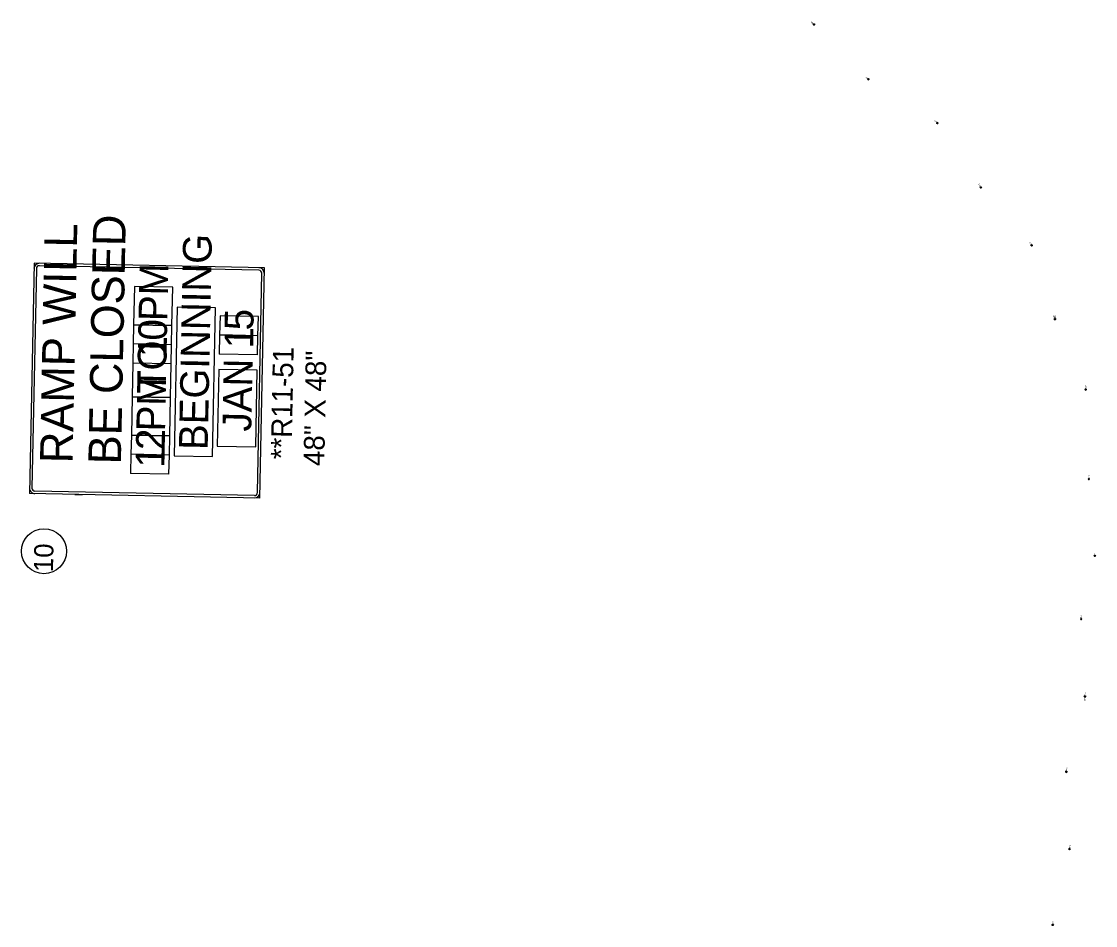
# Model space of a CAD drawing. Extents: x 335726 to 369746, y 119154 to 200788.
# Drawn here: x 351741 to 360135, y 171246 to 178312 of the extents above; entities that cross this region are included whole.
import ezdxf

# ---------------------------------------------------------------- set-up
doc = ezdxf.new("R2010")
doc.units = 0
for name, color, linetype in [('CA-TEXT', 7, 'Continuous'), ('E_SOIL_BORE1 [KAPUR_CADDS_LEVELS]', 7, 'Continuous'), ('E_SOIL_BORE2 [KAPUR_CADDS_LEVELS]', 7, 'Continuous'), ('P_MARK', 7, 'Continuous'), ('P_SGN_Cell', 7, 'Continuous')]:
    doc.layers.add(name, color=color, linetype=linetype)

msp = doc.modelspace()

# ---------------------------------------------------------------- linework, layer by layer
at = {"layer": 'CA-TEXT'}
msp.add_circle((351916.8, 174171.5), 175.9, dxfattribs=at)
at = {"layer": 'P_MARK'}
for p, q in [((357929.4, 178289.2), (357939.4, 178289.2)), ((357934.4, 178294.2), (357934.4, 178284.2)), ((358358.8, 177866.6), (358358.8, 177856.6)), ((358353.8, 177861.6), (358363.8, 177861.6)), ((358893.7, 177517.5), (358903.7, 177517.5)), ((358898.7, 177522.5), (358898.7, 177512.5)), ((359233.3, 177015.2), (359243.3, 177015.2)), ((359238.3, 177020.2), (359238.3, 177010.2)), ((359630.4, 176562.4), (359640.4, 176562.4)), ((359635.4, 176567.4), (359635.4, 176557.4)), ((359812.5, 175985.9), (359822.5, 175985.9)), ((359817.5, 175990.9), (359817.5, 175980.9)), ((360052.2, 175435.6), (360062.2, 175435.6)), ((360057.2, 175440.6), (360057.2, 175430.6)), ((360077.6, 174734.7), (360087.6, 174734.7)), ((360082.6, 174739.7), (360082.6, 174729.7)), ((360124, 174136), (360134, 174136)), ((360129, 174141), (360129, 174131)), ((360017.5, 173640.8), (360027.5, 173640.8)), ((360022.5, 173645.8), (360022.5, 173635.8)), ((360047.1, 173036.8), (360057.1, 173036.8)), ((360052.1, 173041.8), (360052.1, 173031.8)), ((359901.4, 172447.6), (359911.4, 172447.6)), ((359906.4, 172452.6), (359906.4, 172442.6)), ((359926.5, 171844), (359936.5, 171844)), ((359931.5, 171849), (359931.5, 171839)), ((359795.3, 171250.9), (359805.3, 171250.9)), ((359800.3, 171255.9), (359800.3, 171245.9))]:
    msp.add_line(p, q, dxfattribs=at)
for centre in [(357934.4, 178289.2), (358358.8, 177861.6), (358898.7, 177517.5), (359238.3, 177015.2), (359635.4, 176562.4), (359817.5, 175985.9), (360057.2, 175435.6), (360082.6, 174734.7), (360129, 174136), (360022.5, 173640.8), (360052.1, 173036.8), (359906.4, 172447.6), (359931.5, 171844), (359800.3, 171250.9)]:
    msp.add_circle(centre, 5, dxfattribs=at)
for centre, radius, start, end in [((357934.4, 178289.2), 4.5, 89.98693, 179.98693), ((357934.4, 178289.2), 4, 89.98693, 179.98693), ((357934.4, 178289.2), 3.5, 89.98693, 179.98693), ((357934.4, 178289.2), 3, 89.98693, 179.98693), ((357934.4, 178289.2), 2.5, 89.98693, 179.98693), ((357934.4, 178289.2), 2, 89.98693, 179.98693), ((357934.4, 178289.2), 1.5, 89.98693, 179.98693), ((357934.4, 178289.2), 1, 89.98693, 179.98693), ((357934.4, 178289.2), 0.5, 89.98693, 179.98693), ((357934.4, 178289.2), 4.5, 269.98693, 359.98693), ((357934.4, 178289.2), 4, 269.98693, 359.98693), ((357934.4, 178289.2), 3.5, 269.98693, 359.98693), ((357934.4, 178289.2), 3, 269.98693, 359.98693), ((357934.4, 178289.2), 2.5, 269.98693, 359.98693), ((357934.4, 178289.2), 2, 269.98693, 359.98693), ((357934.4, 178289.2), 1.5, 269.98693, 359.98693), ((357934.4, 178289.2), 1, 269.98693, 359.98693), ((357934.4, 178289.2), 0.5, 269.98693, 359.98693), ((358358.8, 177861.6), 4.5, 89.98693, 179.98693), ((358358.8, 177861.6), 4, 89.98693, 179.98693), ((358358.8, 177861.6), 3.5, 89.98693, 179.98693), ((358358.8, 177861.6), 3, 89.98693, 179.98693), ((358358.8, 177861.6), 2.5, 89.98693, 179.98693), ((358358.8, 177861.6), 2, 89.98693, 179.98693), ((358358.8, 177861.6), 1.5, 89.98693, 179.98693), ((358358.8, 177861.6), 1, 89.98693, 179.98693), ((358358.8, 177861.6), 0.5, 89.98693, 179.98693), ((358358.8, 177861.6), 4.5, 269.98693, 359.98693), ((358358.8, 177861.6), 4, 269.98693, 359.98693), ((358358.8, 177861.6), 3.5, 269.98693, 359.98693), ((358358.8, 177861.6), 3, 269.98693, 359.98693), ((358358.8, 177861.6), 2.5, 269.98693, 359.98693), ((358358.8, 177861.6), 2, 269.98693, 359.98693), ((358358.8, 177861.6), 1.5, 269.98693, 359.98693), ((358358.8, 177861.6), 1, 269.98693, 359.98693), ((358358.8, 177861.6), 0.5, 269.98693, 359.98693), ((358898.7, 177517.5), 4.5, 89.98693, 179.98693), ((358898.7, 177517.5), 4, 89.98693, 179.98693), ((358898.7, 177517.5), 3.5, 89.98693, 179.98693), ((358898.7, 177517.5), 3, 89.98693, 179.98693), ((358898.7, 177517.5), 2.5, 89.98693, 179.98693), ((358898.7, 177517.5), 2, 89.98693, 179.98693), ((358898.7, 177517.5), 1.5, 89.98693, 179.98693), ((358898.7, 177517.5), 1, 89.98693, 179.98693), ((358898.7, 177517.5), 0.5, 89.98693, 179.98693), ((358898.7, 177517.5), 4.5, 269.98693, 359.98693), ((358898.7, 177517.5), 4, 269.98693, 359.98693), ((358898.7, 177517.5), 3.5, 269.98693, 359.98693), ((358898.7, 177517.5), 3, 269.98693, 359.98693), ((358898.7, 177517.5), 2.5, 269.98693, 359.98693), ((358898.7, 177517.5), 2, 269.98693, 359.98693), ((358898.7, 177517.5), 1.5, 269.98693, 359.98693), ((358898.7, 177517.5), 1, 269.98693, 359.98693), ((358898.7, 177517.5), 0.5, 269.98693, 359.98693), ((359238.3, 177015.2), 4.5, 89.98693, 179.98693), ((359238.3, 177015.2), 4, 89.98693, 179.98693), ((359238.3, 177015.2), 3.5, 89.98693, 179.98693), ((359238.3, 177015.2), 3, 89.98693, 179.98693), ((359238.3, 177015.2), 2.5, 89.98693, 179.98693), ((359238.3, 177015.2), 2, 89.98693, 179.98693), ((359238.3, 177015.2), 1.5, 89.98693, 179.98693), ((359238.3, 177015.2), 1, 89.98693, 179.98693), ((359238.3, 177015.2), 0.5, 89.98693, 179.98693), ((359238.3, 177015.2), 4.5, 269.98693, 359.98693), ((359238.3, 177015.2), 4, 269.98693, 359.98693), ((359238.3, 177015.2), 3.5, 269.98693, 359.98693), ((359238.3, 177015.2), 3, 269.98693, 359.98693), ((359238.3, 177015.2), 2.5, 269.98693, 359.98693), ((359238.3, 177015.2), 2, 269.98693, 359.98693), ((359238.3, 177015.2), 1.5, 269.98693, 359.98693), ((359238.3, 177015.2), 1, 269.98693, 359.98693), ((359238.3, 177015.2), 0.5, 269.98693, 359.98693), ((359635.4, 176562.4), 4.5, 89.98693, 179.98693), ((359635.4, 176562.4), 4, 89.98693, 179.98693), ((359635.4, 176562.4), 3.5, 89.98693, 179.98693), ((359635.4, 176562.4), 3, 89.98693, 179.98693), ((359635.4, 176562.4), 2.5, 89.98693, 179.98693), ((359635.4, 176562.4), 2, 89.98693, 179.98693), ((359635.4, 176562.4), 1.5, 89.98693, 179.98693), ((359635.4, 176562.4), 1, 89.98693, 179.98693), ((359635.4, 176562.4), 0.5, 89.98693, 179.98693), ((359635.4, 176562.4), 4.5, 269.98693, 359.98693), ((359635.4, 176562.4), 4, 269.98693, 359.98693), ((359635.4, 176562.4), 3.5, 269.98693, 359.98693), ((359635.4, 176562.4), 3, 269.98693, 359.98693), ((359635.4, 176562.4), 2.5, 269.98693, 359.98693), ((359635.4, 176562.4), 2, 269.98693, 359.98693), ((359635.4, 176562.4), 1.5, 269.98693, 359.98693), ((359635.4, 176562.4), 1, 269.98693, 359.98693), ((359635.4, 176562.4), 0.5, 269.98693, 359.98693), ((359817.5, 175985.9), 4.5, 89.98693, 179.98693), ((359817.5, 175985.9), 4, 89.98693, 179.98693), ((359817.5, 175985.9), 3.5, 89.98693, 179.98693), ((359817.5, 175985.9), 3, 89.98693, 179.98693), ((359817.5, 175985.9), 2.5, 89.98693, 179.98693), ((359817.5, 175985.9), 2, 89.98693, 179.98693), ((359817.5, 175985.9), 1.5, 89.98693, 179.98693), ((359817.5, 175985.9), 1, 89.98693, 179.98693), ((359817.5, 175985.9), 0.5, 89.98693, 179.98693), ((359817.5, 175985.9), 4.5, 269.98693, 359.98693), ((359817.5, 175985.9), 4, 269.98693, 359.98693), ((359817.5, 175985.9), 3.5, 269.98693, 359.98693), ((359817.5, 175985.9), 3, 269.98693, 359.98693), ((359817.5, 175985.9), 2.5, 269.98693, 359.98693), ((359817.5, 175985.9), 2, 269.98693, 359.98693), ((359817.5, 175985.9), 1.5, 269.98693, 359.98693), ((359817.5, 175985.9), 1, 269.98693, 359.98693), ((359817.5, 175985.9), 0.5, 269.98693, 359.98693), ((360057.2, 175435.6), 4.5, 89.98693, 179.98693), ((360057.2, 175435.6), 4, 89.98693, 179.98693), ((360057.2, 175435.6), 3.5, 89.98693, 179.98693), ((360057.2, 175435.6), 3, 89.98693, 179.98693), ((360057.2, 175435.6), 2.5, 89.98693, 179.98693), ((360057.2, 175435.6), 2, 89.98693, 179.98693), ((360057.2, 175435.6), 1.5, 89.98693, 179.98693), ((360057.2, 175435.6), 1, 89.98693, 179.98693), ((360057.2, 175435.6), 0.5, 89.98693, 179.98693), ((360057.2, 175435.6), 4.5, 269.98693, 359.98693), ((360057.2, 175435.6), 4, 269.98693, 359.98693), ((360057.2, 175435.6), 3.5, 269.98693, 359.98693), ((360057.2, 175435.6), 3, 269.98693, 359.98693), ((360057.2, 175435.6), 2.5, 269.98693, 359.98693), ((360057.2, 175435.6), 2, 269.98693, 359.98693), ((360057.2, 175435.6), 1.5, 269.98693, 359.98693), ((360057.2, 175435.6), 1, 269.98693, 359.98693), ((360057.2, 175435.6), 0.5, 269.98693, 359.98693), ((360082.6, 174734.7), 4.5, 89.98693, 179.98693), ((360082.6, 174734.7), 4, 89.98693, 179.98693), ((360082.6, 174734.7), 3.5, 89.98693, 179.98693), ((360082.6, 174734.7), 3, 89.98693, 179.98693), ((360082.6, 174734.7), 2.5, 89.98693, 179.98693), ((360082.6, 174734.7), 2, 89.98693, 179.98693), ((360082.6, 174734.7), 1.5, 89.98693, 179.98693), ((360082.6, 174734.7), 1, 89.98693, 179.98693), ((360082.6, 174734.7), 0.5, 89.98693, 179.98693), ((360082.6, 174734.7), 4.5, 269.98693, 359.98693), ((360082.6, 174734.7), 4, 269.98693, 359.98693), ((360082.6, 174734.7), 3.5, 269.98693, 359.98693), ((360082.6, 174734.7), 3, 269.98693, 359.98693), ((360082.6, 174734.7), 2.5, 269.98693, 359.98693), ((360082.6, 174734.7), 2, 269.98693, 359.98693), ((360082.6, 174734.7), 1.5, 269.98693, 359.98693), ((360082.6, 174734.7), 1, 269.98693, 359.98693), ((360082.6, 174734.7), 0.5, 269.98693, 359.98693), ((360129, 174136), 4.5, 89.98693, 179.98693), ((360129, 174136), 4, 89.98693, 179.98693), ((360129, 174136), 3.5, 89.98693, 179.98693), ((360129, 174136), 3, 89.98693, 179.98693), ((360129, 174136), 2.5, 89.98693, 179.98693), ((360129, 174136), 2, 89.98693, 179.98693), ((360129, 174136), 1.5, 89.98693, 179.98693), ((360129, 174136), 1, 89.98693, 179.98693), ((360129, 174136), 0.5, 89.98693, 179.98693), ((360129, 174136), 4.5, 269.98693, 359.98693), ((360129, 174136), 4, 269.98693, 359.98693), ((360129, 174136), 3.5, 269.98693, 359.98693), ((360129, 174136), 3, 269.98693, 359.98693), ((360129, 174136), 2.5, 269.98693, 359.98693), ((360129, 174136), 2, 269.98693, 359.98693), ((360129, 174136), 1.5, 269.98693, 359.98693), ((360129, 174136), 1, 269.98693, 359.98693), ((360129, 174136), 0.5, 269.98693, 359.98693), ((360022.5, 173640.8), 4.5, 89.98693, 179.98693), ((360022.5, 173640.8), 4, 89.98693, 179.98693), ((360022.5, 173640.8), 3.5, 89.98693, 179.98693), ((360022.5, 173640.8), 3, 89.98693, 179.98693), ((360022.5, 173640.8), 2.5, 89.98693, 179.98693), ((360022.5, 173640.8), 2, 89.98693, 179.98693), ((360022.5, 173640.8), 1.5, 89.98693, 179.98693), ((360022.5, 173640.8), 1, 89.98693, 179.98693), ((360022.5, 173640.8), 0.5, 89.98693, 179.98693), ((360022.5, 173640.8), 4.5, 269.98693, 359.98693), ((360022.5, 173640.8), 4, 269.98693, 359.98693), ((360022.5, 173640.8), 3.5, 269.98693, 359.98693), ((360022.5, 173640.8), 3, 269.98693, 359.98693), ((360022.5, 173640.8), 2.5, 269.98693, 359.98693), ((360022.5, 173640.8), 2, 269.98693, 359.98693), ((360022.5, 173640.8), 1.5, 269.98693, 359.98693), ((360022.5, 173640.8), 1, 269.98693, 359.98693), ((360022.5, 173640.8), 0.5, 269.98693, 359.98693), ((360052.1, 173036.8), 4.5, 89.98693, 179.98693), ((360052.1, 173036.8), 4, 89.98693, 179.98693), ((360052.1, 173036.8), 3.5, 89.98693, 179.98693), ((360052.1, 173036.8), 3, 89.98693, 179.98693), ((360052.1, 173036.8), 2.5, 89.98693, 179.98693), ((360052.1, 173036.8), 2, 89.98693, 179.98693), ((360052.1, 173036.8), 1.5, 89.98693, 179.98693), ((360052.1, 173036.8), 1, 89.98693, 179.98693), ((360052.1, 173036.8), 0.5, 89.98693, 179.98693), ((360052.1, 173036.8), 4.5, 269.98693, 359.98693), ((360052.1, 173036.8), 4, 269.98693, 359.98693), ((360052.1, 173036.8), 3.5, 269.98693, 359.98693), ((360052.1, 173036.8), 3, 269.98693, 359.98693), ((360052.1, 173036.8), 2.5, 269.98693, 359.98693), ((360052.1, 173036.8), 2, 269.98693, 359.98693), ((360052.1, 173036.8), 1.5, 269.98693, 359.98693), ((360052.1, 173036.8), 1, 269.98693, 359.98693), ((360052.1, 173036.8), 0.5, 269.98693, 359.98693), ((359906.4, 172447.6), 4.5, 89.98693, 179.98693), ((359906.4, 172447.6), 4, 89.98693, 179.98693), ((359906.4, 172447.6), 3.5, 89.98693, 179.98693), ((359906.4, 172447.6), 3, 89.98693, 179.98693), ((359906.4, 172447.6), 2.5, 89.98693, 179.98693), ((359906.4, 172447.6), 2, 89.98693, 179.98693), ((359906.4, 172447.6), 1.5, 89.98693, 179.98693), ((359906.4, 172447.6), 1, 89.98693, 179.98693), ((359906.4, 172447.6), 0.5, 89.98693, 179.98693), ((359906.4, 172447.6), 4.5, 269.98693, 359.98693), ((359906.4, 172447.6), 4, 269.98693, 359.98693), ((359906.4, 172447.6), 3.5, 269.98693, 359.98693), ((359906.4, 172447.6), 3, 269.98693, 359.98693), ((359906.4, 172447.6), 2.5, 269.98693, 359.98693), ((359906.4, 172447.6), 2, 269.98693, 359.98693), ((359906.4, 172447.6), 1.5, 269.98693, 359.98693), ((359906.4, 172447.6), 1, 269.98693, 359.98693), ((359906.4, 172447.6), 0.5, 269.98693, 359.98693), ((359931.5, 171844), 4.5, 89.98693, 179.98693), ((359931.5, 171844), 4, 89.98693, 179.98693), ((359931.5, 171844), 3.5, 89.98693, 179.98693), ((359931.5, 171844), 3, 89.98693, 179.98693), ((359931.5, 171844), 2.5, 89.98693, 179.98693), ((359931.5, 171844), 2, 89.98693, 179.98693), ((359931.5, 171844), 1.5, 89.98693, 179.98693), ((359931.5, 171844), 1, 89.98693, 179.98693), ((359931.5, 171844), 0.5, 89.98693, 179.98693), ((359931.5, 171844), 4.5, 269.98693, 359.98693), ((359931.5, 171844), 4, 269.98693, 359.98693), ((359931.5, 171844), 3.5, 269.98693, 359.98693), ((359931.5, 171844), 3, 269.98693, 359.98693), ((359931.5, 171844), 2.5, 269.98693, 359.98693), ((359931.5, 171844), 2, 269.98693, 359.98693), ((359931.5, 171844), 1.5, 269.98693, 359.98693), ((359931.5, 171844), 1, 269.98693, 359.98693), ((359931.5, 171844), 0.5, 269.98693, 359.98693), ((359800.3, 171250.9), 4.5, 89.98693, 179.98693), ((359800.3, 171250.9), 4, 89.98693, 179.98693), ((359800.3, 171250.9), 3.5, 89.98693, 179.98693), ((359800.3, 171250.9), 3, 89.98693, 179.98693), ((359800.3, 171250.9), 2.5, 89.98693, 179.98693), ((359800.3, 171250.9), 2, 89.98693, 179.98693), ((359800.3, 171250.9), 1.5, 89.98693, 179.98693), ((359800.3, 171250.9), 1, 89.98693, 179.98693), ((359800.3, 171250.9), 0.5, 89.98693, 179.98693), ((359800.3, 171250.9), 4.5, 269.98693, 359.98693), ((359800.3, 171250.9), 4, 269.98693, 359.98693), ((359800.3, 171250.9), 3.5, 269.98693, 359.98693), ((359800.3, 171250.9), 3, 269.98693, 359.98693), ((359800.3, 171250.9), 2.5, 269.98693, 359.98693), ((359800.3, 171250.9), 2, 269.98693, 359.98693), ((359800.3, 171250.9), 1.5, 269.98693, 359.98693), ((359800.3, 171250.9), 1, 269.98693, 359.98693), ((359800.3, 171250.9), 0.5, 269.98693, 359.98693)]:
    msp.add_arc(centre, radius, start, end, dxfattribs=at)
at = {"layer": 'P_SGN_Cell'}
for p, q in [((351839.2, 176422.6), (351802.9, 174623)), ((351857.1, 176380.1), (351822.5, 174664.8)), ((353638.8, 176386.4), (351839.2, 176422.6)), ((353596.2, 176368.5), (351881, 176403)), ((353602.5, 174586.8), (353638.8, 176386.4)), ((353584.6, 174629.3), (353619.2, 176344.6)), ((352623.2, 176241.4), (352617.1, 175941.5)), ((352923.1, 176235.4), (352623.2, 176241.4)), ((352917.1, 175935.5), (352923.1, 176235.4)), ((352957.5, 176079.4), (352934.1, 174917.2)), ((353257.4, 176073.4), (352957.5, 176079.4)), ((353234, 174911.1), (353257.4, 176073.4)), ((352617.1, 175941.5), (352614.1, 175791.5)), ((352917.1, 175935.5), (352617.1, 175941.5)), ((352617.1, 175941.5), (352917.1, 175935.5)), ((352914, 175785.5), (352917.1, 175935.5)), ((353292.3, 176011.5), (353289.2, 175861.5)), ((353592.2, 176005.4), (353292.3, 176011.5)), ((353589.2, 175855.5), (353592.2, 176005.4)), ((353289.2, 175861.5), (353286.2, 175711.5)), ((353589.2, 175855.5), (353289.2, 175861.5)), ((353590.5, 175856.1), (353290.6, 175862.1)), ((353586.2, 175705.5), (353589.2, 175855.5)), ((352614.1, 175791.5), (352611.1, 175641.6)), ((352914, 175785.5), (352614.1, 175791.5)), ((352914, 175785.5), (352614.1, 175791.5)), ((352911, 175635.5), (352914, 175785.5)), ((353586.2, 175705.5), (353286.2, 175711.5)), ((352611.1, 175641.6), (352605.8, 175379.1)), ((352911, 175635.5), (352611.1, 175641.6)), ((352911, 175635.5), (352611.1, 175641.6)), ((352905.7, 175373.1), (352911, 175635.5)), ((353283.4, 175593.1), (353271.3, 174993.2)), ((353583.3, 175587.1), (353283.4, 175593.1)), ((353571.3, 174987.2), (353583.3, 175587.1)), ((352605.8, 175379.1), (352599.8, 175079.2)), ((352605.8, 175379.1), (352905.7, 175373.1)), ((352905.7, 175373.1), (352605.8, 175379.1)), ((352899.7, 175073.1), (352905.7, 175373.1)), ((352599.8, 175079.2), (352596.7, 174929.2)), ((352899.7, 175073.1), (352599.8, 175079.2)), ((352599.8, 175079.2), (352899.7, 175073.1)), ((352896.7, 174923.2), (352899.7, 175073.1)), ((352596.7, 174929.2), (352593.7, 174779.2)), ((352896.7, 174923.2), (352596.7, 174929.2)), ((352896.7, 174923.2), (352596.7, 174929.2)), ((353271.3, 174993.2), (353571.3, 174987.2)), ((352893.7, 174773.2), (352896.7, 174923.2)), ((352934.1, 174917.2), (353234, 174911.1)), ((352893.7, 174773.2), (352593.7, 174779.2)), ((353602.5, 174586.8), (351802.9, 174623)), ((353560.8, 174606.4), (351845.9, 174640.9)), ((352158.1, 174615.9), (352216.5, 174614.7))]:
    msp.add_line(p, q, dxfattribs=at)
for centre, radius, start, end in [((351880.5, 176379.6), 42.2, 88.84622, 178.84622), ((351880.5, 176379.6), 23.4, 88.84622, 178.84622), ((353595.8, 176345.1), 23.4, 358.84622, 88.84622), ((353595.8, 176345.1), 42.2, 358.84622, 88.84622), ((351845.9, 174664.3), 42.2, 178.84622, 268.84622), ((351845.9, 174664.3), 23.4, 178.84622, 269.87118), ((353561.2, 174629.8), 42.2, 268.84622, 358.84622), ((353561.2, 174629.8), 23.4, 268.84622, 358.84622)]:
    msp.add_arc(centre, radius, start, end, dxfattribs=at)

# ---------------------------------------------------------------- texts
at = {"layer": 'CA-TEXT'}
msp.add_text('10', height=150, rotation=88.84563, dxfattribs=at).set_placement((351986.9, 174007.5))
at = {"layer": 'E_SOIL_BORE1 [KAPUR_CADDS_LEVELS]'}
for s, rotation, p in [('B88', 136.1942, (357933.2, 178297.1)), ('B83', 118.68434, (359238.6, 177024.1)), ('B84', 118.68434, (359636.6, 176570.6)), ('B81', 118.68434, (359820.1, 175993.9)), ('B80', 87.26462, (360133.4, 174142.1)), ('B77', 84.17285, (360026.5, 173648.6)), ('B78', 84.17285, (360057.1, 173042.3)), ('B73', 84.17285, (359806, 171257.5))]:
    msp.add_text(s, height=10, rotation=rotation, dxfattribs=at).set_placement(p)
at = {"layer": 'E_SOIL_BORE2 [KAPUR_CADDS_LEVELS]'}
for s, rotation, p in [('B85', 136.1942, (358357.4, 177869.4)), ('B86', 136.1942, (358898.3, 177525.3)), ('B81', 87.26462, (359822.4, 175993.4)), ('B82', 87.26462, (360062, 175443.3)), ('B79', 87.26462, (360087.5, 174741.4)), ('B78', 84.17285, (360053.8, 173002.7)), ('B75', 84.17285, (359911.5, 172455.4)), ('B76', 84.17285, (359937.1, 171850.2))]:
    msp.add_text(s, height=10, rotation=rotation, dxfattribs=at).set_placement(p)
at = {"layer": 'P_SGN_Cell'}
for s, height, p in [('BE CLOSED', 255, (352517.8, 174848.5)), ('RAMP WILL', 255, (352140, 174857.2)), ('BEGINNING', 225, (353195.8, 174961.6)), ('PM', 225, (352880.2, 175968.4)), ('5', 225, (353552.5, 175896.1)), ('0', 225, (352877.2, 175816.2)), ('1', 225, (353551, 175755.6)), ('TO', 225, (352868.7, 175398.8)), ('1', 225, (352874.5, 175685.6)), ('**R11-51', 162, (353850.7, 174888)), ('48" X 48"', 162, (354106.8, 174836)), ('JAN', 225, (353536.1, 175106)), ('PM', 225, (352862.9, 175106.1)), ('2', 225, (352859.9, 174959.6)), ('1', 225, (352857.2, 174823.3))]:
    msp.add_text(s, height=height, rotation=88.84622, dxfattribs=at).set_placement(p)

doc.saveas('drawing.dxf')
